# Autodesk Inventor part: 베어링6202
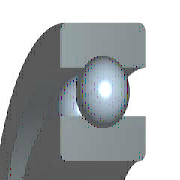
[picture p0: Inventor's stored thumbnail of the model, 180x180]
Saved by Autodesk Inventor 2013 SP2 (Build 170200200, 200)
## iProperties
IsCustomPart: 0
Company: 한국ATC센터
Created: 2014-12
Part Number: 베어링6202
Material: 강, 연강
Description: 깊은 그루브 볼 베어링
Document SubType Name: Modeling
Standard: KS B 2023
Designer: KYOUNG IL JANG
Standards Organization: KS
Language: ko-KR
Size Designation: 6202 - 15 x 35 x 11
Categories: <MemberInstance><Categories><Category DisplayName="샤프트 부품" InternalName="7f7aeb1f-a693-4053-b835-cee3144e0d98" Mnemonic="SHFT"><Category DisplayName="베어링" Inter
Density: 7.86 g/cm^3
Mass: 45.8725 g
Surface Area: 51.5584 cm^2
Volume: 5.83619 cm^3
Author: KYOUNG IL JANG
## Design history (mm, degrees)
sketch "스케치" dims "d0" = 5.2 (= -0.26 x WD + 0.26 x BD)
  geometry: L1 (2.9, 12.5)-(8.1, 12.5); L2 (5.5, 12.5)-(5.5, 9.9); L3 (5.5, 12.5)-(5.5, 15.1); L4 (3.568, 10.76)-(0, 10.76); L5 (0, 7.5)-(11, 7.5); L6 (3.568, 14.24)-(0, 14.24); L7 (0, 17.5)-(11, 17.5); L8 (11, 7.5)-(11, 10.76); L9 (7.432, 10.76)-(11, 10.76); L10 (7.432, 14.24)-(11, 14.24); L11 (11, 17.5)-(11, 14.24); L12 (-1.4, 0)-(8.4, 0) reference; L13 (0, -0.3)-(0, 5.3) reference
  constraints: 22 end point, 4 point on line, 2 collinear, 2 perpendicular, 2 symmetric about line, 1 midpoint, 1 parallel, 14 other
  dimensions: "d9" = 15 diameter of L5 L12 (= WD); "d11" = 35 diameter of L7 L12 (= BD); "d12" = 11 distance between parallel lines of L8 L13 (= KB); "d13" = 21.52 diameter of L9 L12 (= 0.326 x BD + 0.674 x WD)
revolve "본체" stored, may be unused: angle "d6" = 90 deg
revolve "볼" stored, may be unused: angle "d7" = 90 deg
pattern_circular "IDS_ARRAYBALL[SIMPL:T]" dims angle "d3" = 360 deg
body "Solid1"
fillet "모깎기1" dims "d1" = 0.6 (= KRS)
other parameters: "WD" = 15 [user parameter; used in 5 equation terms], "BD" = 35 [user parameter; used in 5 equation terms], "KB" = 11 [user parameter; used in 1 equation term], "KRS" = 0.6 [user parameter; used in 1 equation term], "d4" = 0, "d5" = 0, "d8" = 0, "d14" = 0, "d15" = 0, "BBA" = 0 [user parameter], "BC0" = 3750000 [user parameter], "BC" = 7800000 [user parameter], "BR" = 17.5 (= 0.5 x BD) [user parameter], "WR" = 7.5 (= 0.5 x WD) [user parameter]
